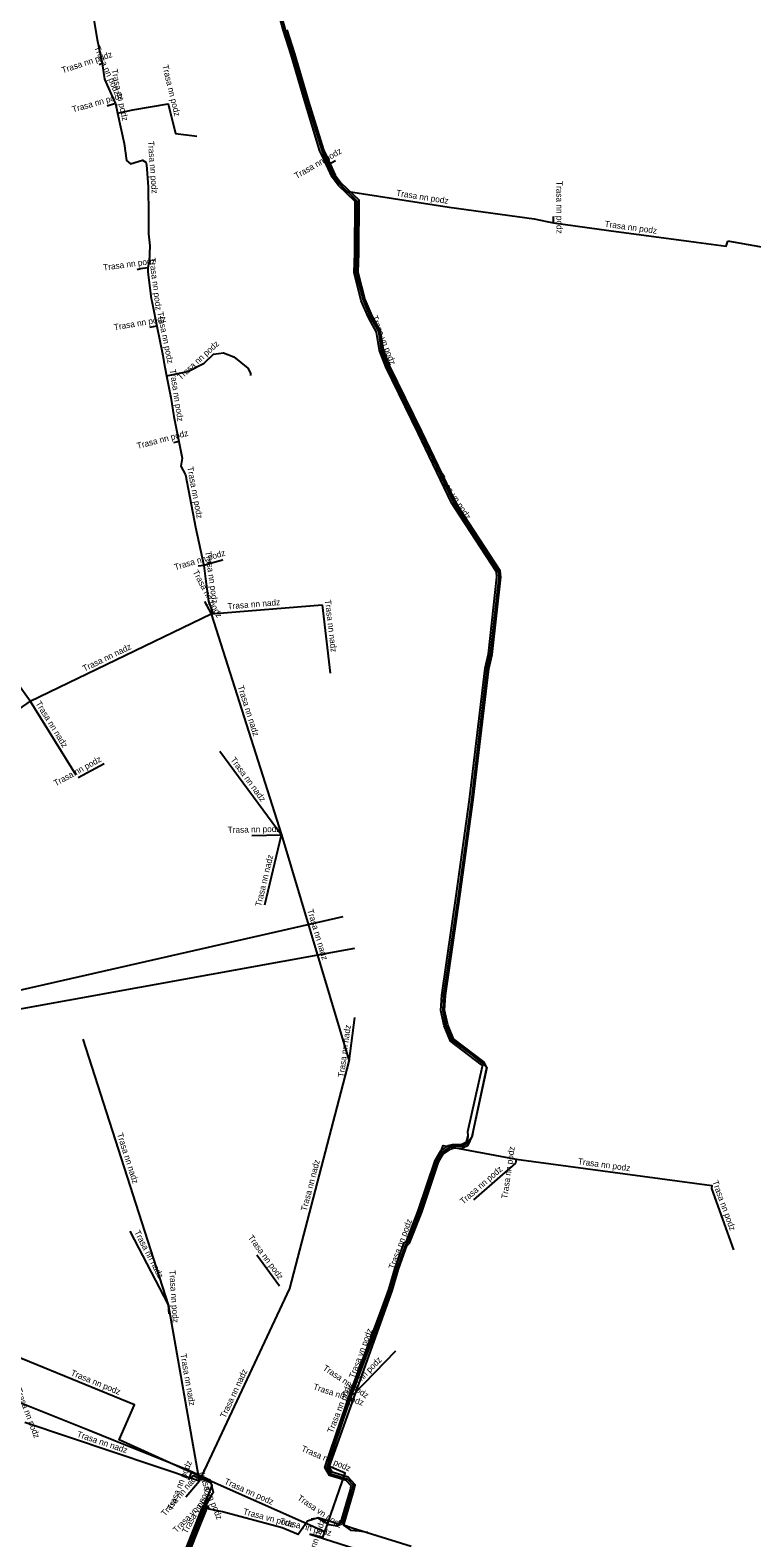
# Model space of a CAD drawing. Extents: x -737281 to -735046, y -1033441 to -1031241.
# Drawn here: x -736134.8 to -736018, y -1032353.4 to -1032109.1 of the extents above; entities that cross this region are included whole.
import ezdxf

# ---------------------------------------------------------------- set-up
doc = ezdxf.new("R2010")
doc.units = 0
for name, color, linetype in [('Level 11', 7, 'Continuous'), ('Level 20', 7, 'Continuous'), ('Level 21', 7, 'Continuous')]:
    doc.layers.add(name, color=color, linetype=linetype)

msp = doc.modelspace()

# ---------------------------------------------------------------- linework, layer by layer
at = {"layer": 'Level 11'}
for p, q in [((-736123.12, -1032114.54), (-736123.63, -1032114.71)), ((-736120.97, -1032121.02), (-736122.34, -1032121.41)), ((-736120.97, -1032121.02), (-736120.64, -1032122.54)), ((-736086.55, -1032130.89), (-736085.35, -1032130.21)), ((-736050.07, -1032140.35), (-736050.08, -1032139.33)), ((-735997.5, -1032147.6), (-736021.85, -1032143.31)), ((-736114.28, -1032157.09), (-736115.45, -1032157.29)), ((-736110.73, -1032175.75), (-736111.6, -1032175.98)), ((-736134.77, -1032217.84), (-736150.66, -1032195.7)), ((-736106.55, -1032201.66), (-736105.47, -1032203.68)), ((-736134.77, -1032217.84), (-736105.47, -1032203.68)), ((-736105.47, -1032203.68), (-736087.5, -1032202.2)), ((-736105.47, -1032203.68), (-736094.1, -1032239.5)), ((-736087.5, -1032202.2), (-736086.2, -1032213.3)), ((-736134.77, -1032217.84), (-736163.82, -1032237.82)), ((-736134.77, -1032217.84), (-736127.4, -1032229.77)), ((-736104.1, -1032225.9), (-736094.1, -1032239.5)), ((-736127, -1032230.2), (-736122.8, -1032227.9)), ((-736098.9, -1032239.6), (-736094.1, -1032239.5)), ((-736096.8, -1032250.8), (-736094.1, -1032239.5)), ((-736094.1, -1032239.5), (-736083.14, -1032276.17)), ((-736204.6, -1032280.12), (-736084.1, -1032252.7)), ((-736082.3, -1032257.9), (-736204.6, -1032280.12)), ((-736083.14, -1032276.17), (-736082.2, -1032269.1)), ((-736112.4, -1032315.6), (-736126.2, -1032272.6)), ((-736092.77, -1032312.96), (-736083.14, -1032276.17)), ((-736056.1, -1032292), (-736056.2, -1032292.7)), ((-736056.2, -1032292.7), (-736063, -1032298.6)), ((-736024.5, -1032296.8), (-736020.9, -1032306.7)), ((-736112.4, -1032315.6), (-736118.61, -1032303.69)), ((-736094.4, -1032312.6), (-736098.1, -1032307.6)), ((-736107.38, -1032344.2), (-736092.77, -1032312.96)), ((-736112.3, -1032317.1), (-736112.4, -1032315.6)), ((-736107.38, -1032344.2), (-736112.4, -1032315.6)), ((-736082.4, -1032330.1), (-736075.6, -1032323.1)), ((-736083.4, -1032331.7), (-736082.7, -1032329.9)), ((-736082.7, -1032329.9), (-736082.4, -1032330.1)), ((-736083.1, -1032331.8), (-736083.4, -1032331.7)), ((-736107.38, -1032344.2), (-736135.63, -1032334.71)), ((-736108.7, -1032342.8), (-736109.17, -1032343.95)), ((-736087.1, -1032352.4), (-736108.7, -1032342.8)), ((-736107.38, -1032344.2), (-736109.6, -1032346.8)), ((-736087.4, -1032353.3), (-736089.49, -1032352.8)), ((-736089.49, -1032352.8), (-736064.32, -1032360.77)), ((-736087.4, -1032353.3), (-736087.1, -1032352.4))]:
    msp.add_line(p, q, dxfattribs=at)
for points in [[(-736100.63, -1032081.55), (-736100.51, -1032082.69), (-736098.51, -1032090.78), (-736095.73, -1032101.21), (-736094.39, -1032105.95), (-736093.52, -1032109.09), (-736091.09, -1032117.08), (-736089.16, -1032123.38), (-736087.59, -1032128.59), (-736087.33, -1032129.16), (-736087.01, -1032129.93), (-736086.55, -1032130.89)], [(-736128.82, -1032093.07), (-736128.59, -1032093.55), (-736126.28, -1032096.27), (-736126.09, -1032097.17), (-736125.89, -1032098.38), (-736125.38, -1032101.95), (-736123.96, -1032110.64), (-736123.12, -1032114.54)], [(-736123.12, -1032114.54), (-736122.75, -1032117.04), (-736121.25, -1032120.48), (-736120.97, -1032121.02)], [(-736120.64, -1032122.54), (-736118.16, -1032122), (-736112.43, -1032121.03), (-736111.27, -1032125.86), (-736108.2, -1032126.23), (-736107.8, -1032126.28)], [(-736120.64, -1032122.54), (-736119.57, -1032127.47), (-736119.2, -1032130.24), (-736118.54, -1032130.76), (-736116.61, -1032130.2), (-736116.04, -1032130.52), (-736115.94, -1032130.95), (-736115.67, -1032134.52), (-736115.62, -1032139.01), (-736115.61, -1032142.1), (-736115.43, -1032144.08), (-736115.53, -1032146.59), (-736115.72, -1032147.61)], [(-736086.55, -1032130.89), (-736085.74, -1032132.58), (-736083.6, -1032135.23), (-736083.25, -1032135.26), (-736066.96, -1032137.8), (-736053.2, -1032139.68), (-736051.15, -1032140.13), (-736050.07, -1032140.35)], [(-736050.07, -1032140.35), (-736041.09, -1032141.58), (-736026.98, -1032143.47), (-736022.09, -1032144.11), (-736021.85, -1032143.31)], [(-736115.72, -1032147.61), (-736116.92, -1032147.77), (-736117.45, -1032147.94)], [(-736115.72, -1032147.61), (-736115.73, -1032148.31), (-736115.19, -1032152.58), (-736115.09, -1032153.04), (-736114.28, -1032157.09)], [(-736114.28, -1032157.09), (-736113.31, -1032161.8), (-736113.12, -1032162.84), (-736112.69, -1032165.1)], [(-736112.69, -1032165.1), (-736109.28, -1032164.39), (-736106.62, -1032163.04), (-736105.09, -1032161.63), (-736103.51, -1032161.4), (-736101.81, -1032162.02), (-736099.55, -1032163.9), (-736099.13, -1032164.69), (-736099.09, -1032165.04)], [(-736112.69, -1032165.1), (-736112.02, -1032168.65), (-736111.55, -1032171.69), (-736110.73, -1032175.75)], [(-736110.73, -1032175.75), (-736110.18, -1032178.48), (-736110.39, -1032179.73), (-736109.65, -1032181.17), (-736108.04, -1032189.63), (-736106.67, -1032195.82), (-736107.59, -1032195.94)], [(-736106.67, -1032195.82), (-736106.45, -1032195.72), (-736104.82, -1032195.24), (-736103.83, -1032194.99), (-736103.57, -1032194.87)], [(-736106.67, -1032195.82), (-736106.38, -1032198), (-736105.89, -1032201.6), (-736105.22, -1032203.57), (-736105.47, -1032203.68)], [(-736082.7, -1032329.9), (-736067.9, -1032289.8), (-736056.1, -1032292)], [(-736056.1, -1032292), (-736024.4, -1032296.3), (-736024.5, -1032296.8)], [(-736108.7, -1032342.8), (-736120.4, -1032337.5), (-736117.9, -1032331.8), (-736145.1, -1032320.7)], [(-736087.1, -1032352.4), (-736083.8, -1032342.9), (-736086.6, -1032341.7), (-736083.4, -1032331.7)], [(-736126.97, -1032401.23), (-736126.66, -1032400.94), (-736124.02, -1032394.06), (-736122.39, -1032389.72), (-736121.53, -1032387.42), (-736119.66, -1032382.46), (-736118.28, -1032378.98), (-736113.66, -1032366.37), (-736111.35, -1032360.3), (-736110.71, -1032358.52), (-736108.34, -1032352.6), (-736107.65, -1032350.68), (-736105.32, -1032344.88), (-736105.65, -1032344.42), (-736108.44, -1032343.33), (-736109.17, -1032343.95)]]:
    msp.add_lwpolyline(points, dxfattribs=at)
at = {"layer": 'Level 21'}
for q in [(-736105.26, -1032346.18), (-736106.02, -1032348.13)]:
    msp.add_line((-736106.69, -1032348.82), q, dxfattribs=at)
for points in [[(-736084.89, -1032351.14), (-736084.63, -1032351.16), (-736084.47, -1032350.57), (-736084.35, -1032350.34), (-736082.95, -1032345.57), (-736082.84, -1032344.94), (-736083.62, -1032344.09), (-736086.31, -1032343.27), (-736087.06, -1032342), (-736083.65, -1032331.83), (-736082.94, -1032329.76), (-736080.75, -1032324.06), (-736077.8, -1032316.1), (-736076.73, -1032313.15), (-736075.71, -1032309.64), (-736074.3, -1032305.71), (-736073.87, -1032305.3), (-736071.96, -1032300.41), (-736069.21, -1032292.25), (-736068.31, -1032290.67), (-736067.04, -1032289.82), (-736066.41, -1032289.65), (-736064.92, -1032289.62), (-736064.15, -1032289.24), (-736063.87, -1032288.25), (-736063.94, -1032287.52), (-736061.54, -1032276.97), (-736061.71, -1032276.75), (-736066.76, -1032272.91), (-736067.77, -1032270.43), (-736068.3, -1032267.95), (-736068.15, -1032265.46), (-736065.74, -1032249), (-736063.65, -1032233.75), (-736061.14, -1032212.46), (-736060.58, -1032210.15), (-736059.22, -1032197.72), (-736059.3, -1032196.89), (-736066, -1032186.61), (-736066.55, -1032185.67), (-736071.99, -1032174.41), (-736077.22, -1032163.66), (-736078.25, -1032161.03), (-736078.7, -1032158.05), (-736080.02, -1032155.68), (-736081.18, -1032152.96), (-736082.34, -1032148.4), (-736082.24, -1032145.22), (-736082.18, -1032136.89), (-736084.94, -1032134.23), (-736085.92, -1032132.92), (-736087.23, -1032129.99), (-736087.87, -1032128.7), (-736090.27, -1032120.85), (-736092.54, -1032113.13), (-736093.79, -1032109.22), (-736094.73, -1032105.79)], [(-736094.35, -1032106.05), (-736093.5, -1032109.14), (-736092.26, -1032113.04), (-736089.99, -1032120.77), (-736087.57, -1032128.61), (-736087.32, -1032129.28), (-736086.96, -1032129.86), (-736085.66, -1032132.76), (-736084.71, -1032134.03), (-736081.88, -1032136.76), (-736081.94, -1032145.23), (-736082.04, -1032148.36), (-736080.9, -1032152.86), (-736079.74, -1032155.55), (-736078.41, -1032157.95), (-736077.96, -1032160.95), (-736076.95, -1032163.54), (-736071.72, -1032174.28), (-736066.28, -1032185.53), (-736065.75, -1032186.45), (-736059.01, -1032196.79), (-736058.92, -1032197.72), (-736060.29, -1032210.2), (-736060.84, -1032212.52), (-736063.35, -1032233.79), (-736065.44, -1032249.05), (-736067.85, -1032265.49), (-736067.99, -1032267.93), (-736067.48, -1032270.35), (-736066.52, -1032272.72), (-736063.24, -1032275.17), (-736061.53, -1032276.51), (-736060.87, -1032277.18), (-736063.12, -1032287.65), (-736063.22, -1032288.34), (-736064.01, -1032289.51), (-736063.87, -1032288.25), (-736063.94, -1032287.52), (-736061.54, -1032276.97), (-736061.53, -1032276.51)], [(-736093.21, -1032109.05), (-736091.97, -1032112.95), (-736089.7, -1032120.68), (-736087.31, -1032128.48), (-736086.69, -1032129.73), (-736085.4, -1032132.61), (-736084.49, -1032133.83), (-736081.58, -1032136.63), (-736081.64, -1032145.23), (-736081.74, -1032148.33), (-736080.61, -1032152.76), (-736079.47, -1032155.41), (-736078.12, -1032157.85), (-736077.66, -1032160.88), (-736076.67, -1032163.42), (-736071.45, -1032174.15), (-736066.02, -1032185.39), (-736065.49, -1032186.3)], [(-736073.13, -1032354.75), (-736082.64, -1032351.83), (-736083.92, -1032351.36), (-736083.99, -1032351.24), (-736082.36, -1032345.71), (-736082.19, -1032344.76), (-736083.29, -1032343.56), (-736085.91, -1032342.76), (-736086.4, -1032341.93), (-736076.16, -1032313.34), (-736075.14, -1032309.82), (-736073.79, -1032306.04), (-736073.36, -1032305.65), (-736071.4, -1032300.61), (-736068.66, -1032292.49), (-736067.86, -1032291.09), (-736066.79, -1032290.38), (-736066.33, -1032290.25), (-736064.78, -1032290.21), (-736063.88, -1032289.78), (-736063.22, -1032288.34), (-736060.87, -1032277.18), (-736061.35, -1032276.27), (-736066.27, -1032272.54), (-736067.19, -1032270.26), (-736067.69, -1032267.9), (-736067.55, -1032265.52), (-736065.15, -1032249.09), (-736063.05, -1032233.82), (-736060.55, -1032212.57), (-736059.99, -1032210.25), (-736058.61, -1032197.72), (-736058.72, -1032196.69), (-736065.49, -1032186.3)], [(-736105.26, -1032346.18), (-736105.13, -1032346.01), (-736105.59, -1032344.09), (-736109.08, -1032342.46), (-736121.23, -1032337.61), (-736125.23, -1032336.01), (-736136.05, -1032331.69), (-736140.72, -1032329.83), (-736148.99, -1032326.55), (-736161.99, -1032321.31), (-736177.06, -1032315.57), (-736190.99, -1032310.32), (-736201.66, -1032305.29), (-736206.85, -1032302.88), (-736207.01, -1032301.88), (-736203.61, -1032294.92), (-736199.01, -1032288.84), (-736198.85, -1032287.61), (-736202.9, -1032284.34), (-736206.92, -1032280.73), (-736206.53, -1032280.07), (-736204.66, -1032280.06)], [(-736064.01, -1032289.51), (-736064.85, -1032289.92), (-736066.37, -1032289.95), (-736066.92, -1032290.1), (-736068.08, -1032290.88), (-736068.93, -1032292.37), (-736071.68, -1032300.51), (-736073.62, -1032305.47), (-736074.04, -1032305.88), (-736075.42, -1032309.73), (-736076.44, -1032313.24), (-736077.52, -1032316.21), (-736080.47, -1032324.17), (-736082.66, -1032329.86), (-736082.9, -1032330.8), (-736083.37, -1032331.93), (-736086.73, -1032341.96), (-736086.11, -1032343.02), (-736083.46, -1032343.82), (-736082.52, -1032344.85), (-736082.66, -1032345.64), (-736084.07, -1032350.45), (-736084.2, -1032350.71), (-736084.05, -1032351.34), (-736082.92, -1032352.14), (-736081.54, -1032352.23), (-736080.14, -1032352.46)], [(-736110.88, -1032358.48), (-736108.54, -1032352.59), (-736107.02, -1032348.7), (-736105.26, -1032346.18)], [(-736106.02, -1032348.13), (-736106.37, -1032348.95), (-736107.89, -1032352.85), (-736110.23, -1032358.74)], [(-736105.24, -1032348.83), (-736105.79, -1032348.72), (-736106.02, -1032348.13)], [(-736106.69, -1032348.82), (-736108.22, -1032352.72), (-736110.55, -1032358.61), (-736115, -1032370.1), (-736119.58, -1032382.7)], [(-736084.89, -1032351.14), (-736088.17, -1032350.13), (-736089.9, -1032350.66), (-736091.41, -1032352.84), (-736093.97, -1032351.76), (-736103.64, -1032349.17), (-736105.24, -1032348.83)], [(-736084.2, -1032350.71), (-736085.1, -1032351.47), (-736086.4, -1032351.26), (-736087.15, -1032350.76), (-736088.18, -1032350.2), (-736089.29, -1032350.36)]]:
    msp.add_lwpolyline(points, dxfattribs=at)

# ---------------------------------------------------------------- texts
at = {"layer": 'Level 20'}
for s, rotation, p in [('Trasa nn podz', 18.1675, (-736129.5, -1032116.11)), ('Trasa nn podz', 293.5559, (-736124.44, -1032111.92)), ('Trasa nn podz', 282.1128, (-736121.64, -1032115.53)), ('Trasa nn podz', 283.5531, (-736113.41, -1032114.85)), ('Trasa nn podz', 15.8848, (-736127.84, -1032122.46)), ('Trasa nn podz', 274.3459, (-736115.73, -1032127.1)), ('Trasa nn podz', 29.7294, (-736091.66, -1032133.23)), ('Trasa nn podz', 351.1286, (-736075.58, -1032135.95)), ('Trasa nn podz', 270.2245, (-736049.6, -1032133.55)), ('Trasa nn podz', 352.3782, (-736041.84, -1032140.97)), ('Trasa nn podz', 7.6324, (-736122.9, -1032148.07)), ('Trasa nn podz', 277.1135, (-736115.5, -1032146.08)), ('Trasa nn podz', 9.6518, (-736121.15, -1032157.75)), ('Trasa nn podz', 281.5949, (-736114.23, -1032154.83)), ('Trasa vn podz', 291.2987, (-736079.53, -1032155.55)), ('Trasa nn podz', 42.7809, (-736110.39, -1032165.86)), ('Trasa nn podz', 278.6981, (-736112.2, -1032164.14)), ('Trasa nn podz', 14.5412, (-736117.38, -1032176.96)), ('Trasa nn podz', 280.7669, (-736109.38, -1032179.92)), ('Trasa vn podz', 303.0777, (-736068.8, -1032181.39)), ('Trasa nn podz', 16.3249, (-736111.3, -1032196.62)), ('Trasa nn podz', 277.7247, (-736106.47, -1032193.58)), ('Trasa nn podz', 298.0313, (-736108.52, -1032196.89)), ('Trasa nn nadz', 4.7117, (-736102.79, -1032202.96)), ('Trasa nn nadz', 276.6799, (-736087.08, -1032201.45)), ('Trasa nn nadz', 25.791, (-736126, -1032213.05)), ('Trasa nn nadz', 287.6095, (-736101.21, -1032215.45)), ('Trasa nn nadz', 301.7065, (-736133.96, -1032218.19)), ('Trasa nn podz', 28.706, (-736130.65, -1032231.63)), ('Trasa nn nadz', 306.3268, (-736102.42, -1032227.34)), ('Trasa nn podz', 1.1935, (-736102.8, -1032239.18)), ('Trasa nn nadz', 76.5618, (-736097.4, -1032251.15)), ('Trasa nn nadz', 286.6405, (-736089.94, -1032251.67)), ('Trasa nn nadz', 82.4266, (-736083.99, -1032278.8)), ('Trasa nn nadz', 287.793, (-736120.75, -1032287.96)), ('Trasa nn nadz', 75.3316, (-736090.03, -1032300.52)), ('Trasa nn podz', 81.8699, (-736057.53, -1032298.5)), ('Trasa nn podz', 352.2752, (-736046.16, -1032292.84)), ('Trasa nn podz', 40.9464, (-736064.68, -1032299.39)), ('Trasa nn podz', 289.9831, (-736024.38, -1032295.67)), ('Trasa nn podz', 69.742, (-736075.87, -1032309.94)), ('Trasa nn nadz', 297.5308, (-736117.97, -1032303.84)), ('Trasa nn podz', 306.5014, (-736099.59, -1032304.75)), ('Trasa nn podz', 273.8141, (-736112.27, -1032310.04)), ('Trasa vn podz', 69.6588, (-736082.28, -1032327.62)), ('Trasa nn nadz', 279.9554, (-736110.48, -1032323.62)), ('Trasa nn podz', 337.8002, (-736128.31, -1032327.01)), ('Trasa nn nadz', 64.9359, (-736103.19, -1032334.06)), ('Trasa nn podz', 326.3099, (-736087.5, -1032326.1)), ('Trasa nn podz', 45.8303, (-736083.74, -1032330.76)), ('Trasa nn podz', 341.5651, (-736089.06, -1032329.29)), ('Trasa nn podz', 68.7495, (-736085.79, -1032336.48)), ('Trasa nn podz', 290.8716, (-736137.14, -1032329.35)), ('Trasa nn nadz', 341.4313, (-736127.31, -1032336.98)), ('Trasa nn podz', 336.8014, (-736090.98, -1032339.28)), ('Trasa nn podz', 68.0532, (-736111.75, -1032349.02)), ('Trasa nn nadz', 49.5078, (-736112.95, -1032349.96)), ('Trasa vn podz', 291.666, (-736107.66, -1032342.66)), ('Trasa vn podz', 61.5403, (-736109.41, -1032352.79)), ('Trasa nn podz', 336.0375, (-736103.44, -1032344.59)), ('Trasa vn podz', 45.8853, (-736111.09, -1032352.64)), ('Trasa vn podz', 326.1162, (-736091.63, -1032347.15)), ('Trasa vn podz', 345.0221, (-736100.39, -1032349.53)), ('Trasa nn podz', 346.5457, (-736094.44, -1032351.1)), ('Trasa nn podz', 71.5651, (-736089.71, -1032358.66))]:
    msp.add_text(s, height=1, rotation=rotation, dxfattribs=at).set_placement(p)

doc.saveas('drawing.dxf')
